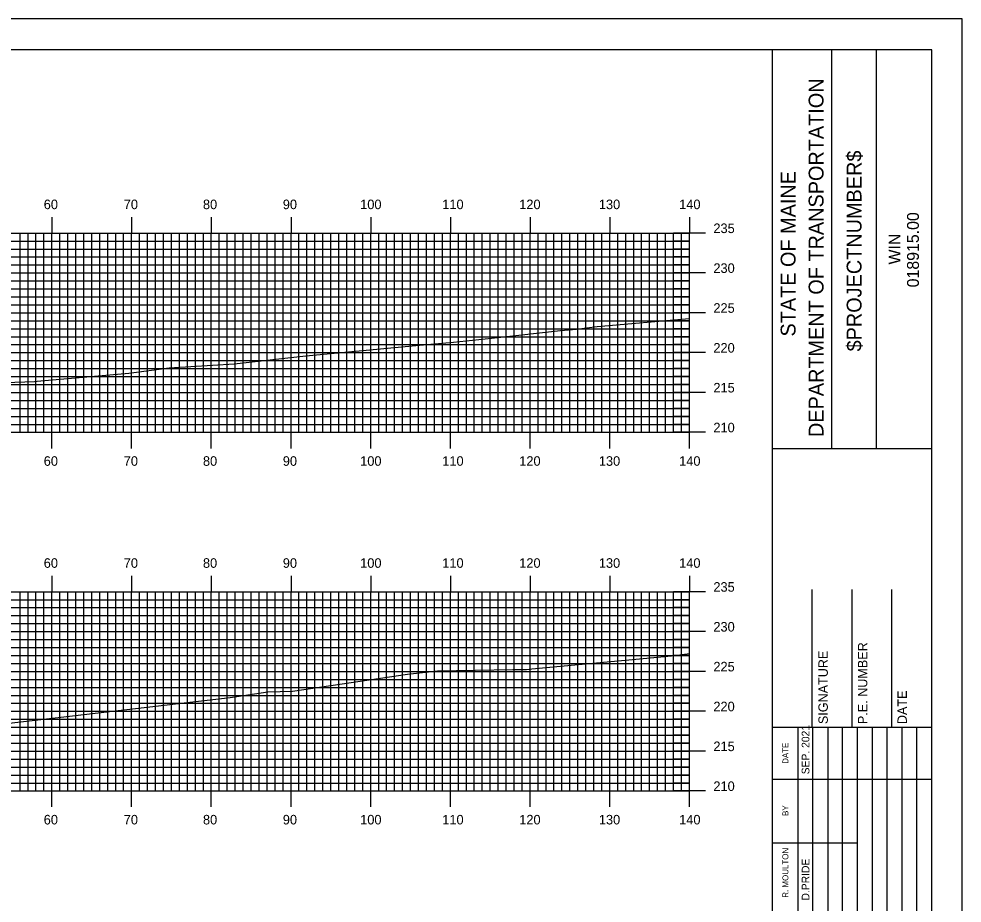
# Model space of a CAD drawing. Extents: x 1818850 to 1819194, y 442591 to 442811.
# Drawn here: x 1819072 to 1819190.4, y 442699.6 to 442810.5 of the extents above; entities that cross this region are included whole.
import ezdxf

# ---------------------------------------------------------------- set-up
doc = ezdxf.new("R2010")
doc.units = 0
for name, color, linetype in [('BORDER', 7, 'Continuous'), ('H_V ANNOTATION', 7, 'Continuous'), ('MAJOR', 7, 'Continuous'), ('MINOR', 7, 'Continuous'), ('PLOT BOUNDARY', 7, 'Continuous'), ('S_Roadway_Centerline', 7, 'Continuous')]:
    doc.layers.add(name, color=color, linetype=linetype)

msp = doc.modelspace()

# ---------------------------------------------------------------- linework, layer by layer
at = {"layer": 'BORDER'}
for p, q in [((1819166.55, 442596.67), (1819166.55, 442806.67)), ((1819174.01, 442756.66), (1819174.01, 442806.66)), ((1819179.6, 442756.66), (1819179.6, 442806.66)), ((1819166.55, 442756.65), (1819186.55, 442756.65)), ((1819171.55, 442721.67), (1819171.55, 442738.97)), ((1819176.55, 442721.67), (1819176.55, 442738.97)), ((1819181.55, 442721.67), (1819181.55, 442738.97)), ((1819166.55, 442721.67), (1819186.55, 442721.67))]:
    msp.add_line(p, q, dxfattribs=at)
msp.add_lwpolyline([(1818866.55, 442596.67), (1819186.55, 442596.67), (1819186.55, 442806.67), (1818866.55, 442806.67)], close=True, dxfattribs=at)
for points in [[(1819169.78, 442715.17), (1819169.78, 442721.67)], [(1819171.65, 442686.68), (1819171.65, 442721.67)], [(1819173.51, 442721.67), (1819173.51, 442686.68)], [(1819175.37, 442686.68), (1819175.37, 442721.67)], [(1819177.24, 442686.68), (1819177.24, 442721.67)], [(1819179.1, 442686.68), (1819179.1, 442721.67)], [(1819180.96, 442686.68), (1819180.96, 442721.67)], [(1819182.83, 442686.68), (1819182.83, 442721.67)], [(1819184.69, 442686.68), (1819184.69, 442721.67)], [(1819169.78, 442686.68), (1819169.78, 442720.26)], [(1819166.55, 442715.17), (1819186.55, 442715.17)], [(1819166.55, 442707.17), (1819169.78, 442707.17)], [(1819169.78, 442707.17), (1819177.23, 442707.17)]]:
    msp.add_lwpolyline(points, dxfattribs=at)
at = {"layer": 'MAJOR'}
for p, q in [((1819076.15, 442785.67), (1819076.15, 442783.67)), ((1819086.15, 442785.67), (1819086.15, 442783.67)), ((1819096.15, 442785.67), (1819096.15, 442783.67)), ((1819106.15, 442785.67), (1819106.15, 442783.67)), ((1819116.15, 442785.67), (1819116.15, 442783.67)), ((1819126.15, 442785.67), (1819126.15, 442783.67)), ((1819136.15, 442785.67), (1819136.15, 442783.67)), ((1819146.15, 442785.67), (1819146.15, 442783.67)), ((1819156.15, 442785.67), (1819156.15, 442783.67)), ((1818876.15, 442783.67), (1819156.15, 442783.67)), ((1818876.15, 442783.67), (1819156.15, 442783.67)), ((1819076.15, 442758.67), (1819076.15, 442783.67)), ((1819086.15, 442758.67), (1819086.15, 442783.67)), ((1819096.15, 442758.67), (1819096.15, 442783.67)), ((1819106.15, 442758.67), (1819106.15, 442783.67)), ((1819116.15, 442758.67), (1819116.15, 442783.67)), ((1819126.15, 442758.67), (1819126.15, 442783.67)), ((1819136.15, 442758.67), (1819136.15, 442783.67)), ((1819146.15, 442758.67), (1819146.15, 442783.67)), ((1819158.16, 442783.67), (1819154.15, 442783.67)), ((1819156.15, 442758.67), (1819156.15, 442783.67)), ((1819156.15, 442758.67), (1819156.15, 442783.67)), ((1818876.15, 442778.67), (1819156.15, 442778.67)), ((1819158.16, 442778.67), (1819154.15, 442778.67)), ((1818876.15, 442773.67), (1819156.15, 442773.67)), ((1819158.16, 442773.67), (1819154.15, 442773.67)), ((1818876.15, 442768.67), (1819156.15, 442768.67)), ((1819158.16, 442768.67), (1819154.15, 442768.67)), ((1818876.15, 442763.67), (1819156.15, 442763.67)), ((1819158.16, 442763.67), (1819154.15, 442763.67)), ((1818876.15, 442758.67), (1819156.15, 442758.67)), ((1818876.15, 442758.67), (1819156.15, 442758.67)), ((1819076.15, 442756.66), (1819076.15, 442758.67)), ((1819086.15, 442756.66), (1819086.15, 442758.67)), ((1819096.15, 442756.66), (1819096.15, 442758.67)), ((1819106.15, 442756.66), (1819106.15, 442758.67)), ((1819116.15, 442756.66), (1819116.15, 442758.67)), ((1819126.15, 442756.66), (1819126.15, 442758.67)), ((1819136.15, 442756.66), (1819136.15, 442758.67)), ((1819146.15, 442756.66), (1819146.15, 442758.67)), ((1819158.16, 442758.67), (1819154.15, 442758.67)), ((1819156.15, 442756.66), (1819156.15, 442758.67)), ((1819076.15, 442740.67), (1819076.15, 442738.67)), ((1819086.15, 442740.67), (1819086.15, 442738.67)), ((1819096.15, 442740.67), (1819096.15, 442738.67)), ((1819106.15, 442740.67), (1819106.15, 442738.67)), ((1819116.15, 442740.67), (1819116.15, 442738.67)), ((1819126.15, 442740.67), (1819126.15, 442738.67)), ((1819136.15, 442740.67), (1819136.15, 442738.67)), ((1819146.15, 442740.67), (1819146.15, 442738.67)), ((1819156.15, 442740.67), (1819156.15, 442738.67)), ((1818876.15, 442738.67), (1819156.15, 442738.67)), ((1818876.15, 442738.67), (1819156.15, 442738.67)), ((1819076.15, 442713.67), (1819076.15, 442738.67)), ((1819086.15, 442713.67), (1819086.15, 442738.67)), ((1819096.15, 442713.67), (1819096.15, 442738.67)), ((1819106.15, 442713.67), (1819106.15, 442738.67)), ((1819116.15, 442713.67), (1819116.15, 442738.67)), ((1819126.15, 442713.67), (1819126.15, 442738.67)), ((1819136.15, 442713.67), (1819136.15, 442738.67)), ((1819146.15, 442713.67), (1819146.15, 442738.67)), ((1819158.16, 442738.67), (1819154.15, 442738.67)), ((1819156.15, 442713.67), (1819156.15, 442738.67)), ((1819156.15, 442713.67), (1819156.15, 442738.67)), ((1818876.15, 442733.67), (1819156.15, 442733.67)), ((1819158.16, 442733.67), (1819154.15, 442733.67)), ((1818876.15, 442728.67), (1819156.15, 442728.67)), ((1819158.16, 442728.67), (1819154.15, 442728.67)), ((1818876.15, 442723.67), (1819156.15, 442723.67)), ((1819158.16, 442723.67), (1819154.15, 442723.67)), ((1818876.15, 442718.67), (1819156.15, 442718.67)), ((1819158.16, 442718.67), (1819154.15, 442718.67)), ((1818876.15, 442713.67), (1819156.15, 442713.67)), ((1818876.15, 442713.67), (1819156.15, 442713.67)), ((1819076.15, 442711.66), (1819076.15, 442713.67)), ((1819086.15, 442711.66), (1819086.15, 442713.67)), ((1819096.15, 442711.66), (1819096.15, 442713.67)), ((1819106.15, 442711.66), (1819106.15, 442713.67)), ((1819116.15, 442711.66), (1819116.15, 442713.67)), ((1819126.15, 442711.66), (1819126.15, 442713.67)), ((1819136.15, 442711.66), (1819136.15, 442713.67)), ((1819146.15, 442711.66), (1819146.15, 442713.67)), ((1819158.16, 442713.67), (1819154.15, 442713.67)), ((1819156.15, 442711.66), (1819156.15, 442713.67))]:
    msp.add_line(p, q, dxfattribs=at)
at = {"layer": 'MINOR'}
for p, q in [((1818876.15, 442782.67), (1819156.15, 442782.67)), ((1819072.15, 442758.67), (1819072.15, 442783.67)), ((1819073.15, 442758.67), (1819073.15, 442783.67)), ((1819074.15, 442758.67), (1819074.15, 442783.67)), ((1819075.15, 442758.67), (1819075.15, 442783.67)), ((1819077.15, 442758.67), (1819077.15, 442783.67)), ((1819078.15, 442758.67), (1819078.15, 442783.67)), ((1819079.15, 442758.67), (1819079.15, 442783.67)), ((1819080.15, 442758.67), (1819080.15, 442783.67)), ((1819081.15, 442758.67), (1819081.15, 442783.67)), ((1819082.15, 442758.67), (1819082.15, 442783.67)), ((1819083.15, 442758.67), (1819083.15, 442783.67)), ((1819084.15, 442758.67), (1819084.15, 442783.67)), ((1819085.15, 442758.67), (1819085.15, 442783.67)), ((1819087.15, 442758.67), (1819087.15, 442783.67)), ((1819088.15, 442758.67), (1819088.15, 442783.67)), ((1819089.15, 442758.67), (1819089.15, 442783.67)), ((1819090.15, 442758.67), (1819090.15, 442783.67)), ((1819091.15, 442758.67), (1819091.15, 442783.67)), ((1819092.15, 442758.67), (1819092.15, 442783.67)), ((1819093.15, 442758.67), (1819093.15, 442783.67)), ((1819094.15, 442758.67), (1819094.15, 442783.67)), ((1819095.15, 442758.67), (1819095.15, 442783.67)), ((1819097.15, 442758.67), (1819097.15, 442783.67)), ((1819098.15, 442758.67), (1819098.15, 442783.67)), ((1819099.15, 442758.67), (1819099.15, 442783.67)), ((1819100.15, 442758.67), (1819100.15, 442783.67)), ((1819101.15, 442758.67), (1819101.15, 442783.67)), ((1819102.15, 442758.67), (1819102.15, 442783.67)), ((1819103.15, 442758.67), (1819103.15, 442783.67)), ((1819104.15, 442758.67), (1819104.15, 442783.67)), ((1819105.15, 442758.67), (1819105.15, 442783.67)), ((1819107.15, 442758.67), (1819107.15, 442783.67)), ((1819108.15, 442758.67), (1819108.15, 442783.67)), ((1819109.15, 442758.67), (1819109.15, 442783.67)), ((1819110.15, 442758.67), (1819110.15, 442783.67)), ((1819111.15, 442758.67), (1819111.15, 442783.67)), ((1819112.15, 442758.67), (1819112.15, 442783.67)), ((1819113.15, 442758.67), (1819113.15, 442783.67)), ((1819114.15, 442758.67), (1819114.15, 442783.67)), ((1819115.15, 442758.67), (1819115.15, 442783.67)), ((1819117.15, 442758.67), (1819117.15, 442783.67)), ((1819118.15, 442758.67), (1819118.15, 442783.67)), ((1819119.15, 442758.67), (1819119.15, 442783.67)), ((1819120.15, 442758.67), (1819120.15, 442783.67)), ((1819121.15, 442758.67), (1819121.15, 442783.67)), ((1819122.15, 442758.67), (1819122.15, 442783.67)), ((1819123.15, 442758.67), (1819123.15, 442783.67)), ((1819124.15, 442758.67), (1819124.15, 442783.67)), ((1819125.15, 442758.67), (1819125.15, 442783.67)), ((1819127.15, 442758.67), (1819127.15, 442783.67)), ((1819128.15, 442758.67), (1819128.15, 442783.67)), ((1819129.15, 442758.67), (1819129.15, 442783.67)), ((1819130.15, 442758.67), (1819130.15, 442783.67)), ((1819131.15, 442758.67), (1819131.15, 442783.67)), ((1819132.15, 442758.67), (1819132.15, 442783.67)), ((1819133.15, 442758.67), (1819133.15, 442783.67)), ((1819134.15, 442758.67), (1819134.15, 442783.67)), ((1819135.15, 442758.67), (1819135.15, 442783.67)), ((1819137.15, 442758.67), (1819137.15, 442783.67)), ((1819138.15, 442758.67), (1819138.15, 442783.67)), ((1819139.15, 442758.67), (1819139.15, 442783.67)), ((1819140.15, 442758.67), (1819140.15, 442783.67)), ((1819141.15, 442758.67), (1819141.15, 442783.67)), ((1819142.15, 442758.67), (1819142.15, 442783.67)), ((1819143.15, 442758.67), (1819143.15, 442783.67)), ((1819144.15, 442758.67), (1819144.15, 442783.67)), ((1819145.15, 442758.67), (1819145.15, 442783.67)), ((1819147.15, 442758.67), (1819147.15, 442783.67)), ((1819148.15, 442758.67), (1819148.15, 442783.67)), ((1819149.15, 442758.67), (1819149.15, 442783.67)), ((1819150.15, 442758.67), (1819150.15, 442783.67)), ((1819151.15, 442758.67), (1819151.15, 442783.67)), ((1819152.15, 442758.67), (1819152.15, 442783.67)), ((1819153.15, 442758.67), (1819153.15, 442783.67)), ((1819154.15, 442758.67), (1819154.15, 442783.67)), ((1819156.15, 442782.67), (1819154.15, 442782.67)), ((1819155.15, 442758.67), (1819155.15, 442783.67)), ((1818876.15, 442781.67), (1819156.15, 442781.67)), ((1819156.15, 442781.67), (1819154.15, 442781.67)), ((1818876.15, 442780.67), (1819156.15, 442780.67)), ((1819156.15, 442780.67), (1819154.15, 442780.67)), ((1818876.15, 442779.67), (1819156.15, 442779.67)), ((1819156.15, 442779.67), (1819154.15, 442779.67)), ((1818876.15, 442777.67), (1819156.15, 442777.67)), ((1819156.15, 442777.67), (1819154.15, 442777.67)), ((1818876.15, 442776.67), (1819156.15, 442776.67)), ((1818876.15, 442775.67), (1819156.15, 442775.67)), ((1819156.15, 442776.67), (1819154.15, 442776.67)), ((1819156.15, 442775.67), (1819154.15, 442775.67)), ((1818876.15, 442774.67), (1819156.15, 442774.67)), ((1819156.15, 442774.67), (1819154.15, 442774.67)), ((1818876.15, 442772.67), (1819156.15, 442772.67)), ((1819156.15, 442772.67), (1819154.15, 442772.67)), ((1818876.15, 442771.67), (1819156.15, 442771.67)), ((1819156.15, 442771.67), (1819154.15, 442771.67)), ((1818876.15, 442770.67), (1819156.15, 442770.67)), ((1818876.15, 442769.67), (1819156.15, 442769.67)), ((1819156.15, 442770.67), (1819154.15, 442770.67)), ((1819156.15, 442769.67), (1819154.15, 442769.67)), ((1818876.15, 442767.67), (1819156.15, 442767.67)), ((1819156.15, 442767.67), (1819154.15, 442767.67)), ((1818876.15, 442766.67), (1819156.15, 442766.67)), ((1819156.15, 442766.67), (1819154.15, 442766.67)), ((1818876.15, 442765.67), (1819156.15, 442765.67)), ((1819156.15, 442765.67), (1819154.15, 442765.67)), ((1818876.15, 442764.67), (1819156.15, 442764.67)), ((1819156.15, 442764.67), (1819154.15, 442764.67)), ((1818876.15, 442762.67), (1819156.15, 442762.67)), ((1819156.15, 442762.67), (1819154.15, 442762.67)), ((1818876.15, 442761.67), (1819156.15, 442761.67)), ((1819156.15, 442761.67), (1819154.15, 442761.67)), ((1818876.15, 442760.67), (1819156.15, 442760.67)), ((1819156.15, 442760.67), (1819154.15, 442760.67)), ((1818876.15, 442759.67), (1819156.15, 442759.67)), ((1819156.15, 442759.67), (1819154.15, 442759.67)), ((1819072.15, 442713.67), (1819072.15, 442738.67)), ((1819073.15, 442713.67), (1819073.15, 442738.67)), ((1819074.15, 442713.67), (1819074.15, 442738.67)), ((1819075.15, 442713.67), (1819075.15, 442738.67)), ((1819077.15, 442713.67), (1819077.15, 442738.67)), ((1819078.15, 442713.67), (1819078.15, 442738.67)), ((1819079.15, 442713.67), (1819079.15, 442738.67)), ((1819080.15, 442713.67), (1819080.15, 442738.67)), ((1819081.15, 442713.67), (1819081.15, 442738.67)), ((1819082.15, 442713.67), (1819082.15, 442738.67)), ((1819083.15, 442713.67), (1819083.15, 442738.67)), ((1819084.15, 442713.67), (1819084.15, 442738.67)), ((1819085.15, 442713.67), (1819085.15, 442738.67)), ((1819087.15, 442713.67), (1819087.15, 442738.67)), ((1819088.15, 442713.67), (1819088.15, 442738.67)), ((1819089.15, 442713.67), (1819089.15, 442738.67)), ((1819090.15, 442713.67), (1819090.15, 442738.67)), ((1819091.15, 442713.67), (1819091.15, 442738.67)), ((1819092.15, 442713.67), (1819092.15, 442738.67)), ((1819093.15, 442713.67), (1819093.15, 442738.67)), ((1819094.15, 442713.67), (1819094.15, 442738.67)), ((1819095.15, 442713.67), (1819095.15, 442738.67)), ((1819097.15, 442713.67), (1819097.15, 442738.67)), ((1819098.15, 442713.67), (1819098.15, 442738.67)), ((1819099.15, 442713.67), (1819099.15, 442738.67)), ((1819100.15, 442713.67), (1819100.15, 442738.67)), ((1819101.15, 442713.67), (1819101.15, 442738.67)), ((1819102.15, 442713.67), (1819102.15, 442738.67)), ((1819103.15, 442713.67), (1819103.15, 442738.67)), ((1819104.15, 442713.67), (1819104.15, 442738.67)), ((1819105.15, 442713.67), (1819105.15, 442738.67)), ((1819107.15, 442713.67), (1819107.15, 442738.67)), ((1819108.15, 442713.67), (1819108.15, 442738.67)), ((1819109.15, 442713.67), (1819109.15, 442738.67)), ((1819110.15, 442713.67), (1819110.15, 442738.67)), ((1819111.15, 442713.67), (1819111.15, 442738.67)), ((1819112.15, 442713.67), (1819112.15, 442738.67)), ((1819113.15, 442713.67), (1819113.15, 442738.67)), ((1819114.15, 442713.67), (1819114.15, 442738.67)), ((1819115.15, 442713.67), (1819115.15, 442738.67)), ((1819117.15, 442713.67), (1819117.15, 442738.67)), ((1819118.15, 442713.67), (1819118.15, 442738.67)), ((1819119.15, 442713.67), (1819119.15, 442738.67)), ((1819120.15, 442713.67), (1819120.15, 442738.67)), ((1819121.15, 442713.67), (1819121.15, 442738.67)), ((1819122.15, 442713.67), (1819122.15, 442738.67)), ((1819123.15, 442713.67), (1819123.15, 442738.67)), ((1819124.15, 442713.67), (1819124.15, 442738.67)), ((1819125.15, 442713.67), (1819125.15, 442738.67)), ((1819127.15, 442713.67), (1819127.15, 442738.67)), ((1819128.15, 442713.67), (1819128.15, 442738.67)), ((1819129.15, 442713.67), (1819129.15, 442738.67)), ((1819130.15, 442713.67), (1819130.15, 442738.67)), ((1819131.15, 442713.67), (1819131.15, 442738.67)), ((1819132.15, 442713.67), (1819132.15, 442738.67)), ((1819133.15, 442713.67), (1819133.15, 442738.67)), ((1819134.15, 442713.67), (1819134.15, 442738.67)), ((1819135.15, 442713.67), (1819135.15, 442738.67)), ((1819137.15, 442713.67), (1819137.15, 442738.67)), ((1819138.15, 442713.67), (1819138.15, 442738.67)), ((1819139.15, 442713.67), (1819139.15, 442738.67)), ((1819140.15, 442713.67), (1819140.15, 442738.67)), ((1819141.15, 442713.67), (1819141.15, 442738.67)), ((1819142.15, 442713.67), (1819142.15, 442738.67)), ((1819143.15, 442713.67), (1819143.15, 442738.67)), ((1819144.15, 442713.67), (1819144.15, 442738.67)), ((1819145.15, 442713.67), (1819145.15, 442738.67)), ((1819147.15, 442713.67), (1819147.15, 442738.67)), ((1819148.15, 442713.67), (1819148.15, 442738.67)), ((1819149.15, 442713.67), (1819149.15, 442738.67)), ((1819150.15, 442713.67), (1819150.15, 442738.67)), ((1819151.15, 442713.67), (1819151.15, 442738.67)), ((1819152.15, 442713.67), (1819152.15, 442738.67)), ((1819153.15, 442713.67), (1819153.15, 442738.67)), ((1819154.15, 442713.67), (1819154.15, 442738.67)), ((1819155.15, 442713.67), (1819155.15, 442738.67)), ((1818876.15, 442737.67), (1819156.15, 442737.67)), ((1818876.15, 442736.67), (1819156.15, 442736.67)), ((1819156.15, 442737.67), (1819154.15, 442737.67)), ((1819156.15, 442736.67), (1819154.15, 442736.67)), ((1818876.15, 442735.67), (1819156.15, 442735.67)), ((1819156.15, 442735.67), (1819154.15, 442735.67)), ((1818876.15, 442734.67), (1819156.15, 442734.67)), ((1819156.15, 442734.67), (1819154.15, 442734.67)), ((1818876.15, 442732.67), (1819156.15, 442732.67)), ((1819156.15, 442732.67), (1819154.15, 442732.67)), ((1818876.15, 442731.67), (1819156.15, 442731.67)), ((1818876.15, 442730.67), (1819156.15, 442730.67)), ((1819156.15, 442731.67), (1819154.15, 442731.67)), ((1819156.15, 442730.67), (1819154.15, 442730.67)), ((1818876.15, 442729.67), (1819156.15, 442729.67)), ((1819156.15, 442729.67), (1819154.15, 442729.67)), ((1818876.15, 442727.67), (1819156.15, 442727.67)), ((1819156.15, 442727.67), (1819154.15, 442727.67)), ((1818876.15, 442726.67), (1819156.15, 442726.67)), ((1819156.15, 442726.67), (1819154.15, 442726.67)), ((1818876.15, 442725.67), (1819156.15, 442725.67)), ((1819156.15, 442725.67), (1819154.15, 442725.67)), ((1818876.15, 442724.67), (1819156.15, 442724.67)), ((1819156.15, 442724.67), (1819154.15, 442724.67)), ((1818876.15, 442722.67), (1819156.15, 442722.67)), ((1819156.15, 442722.67), (1819154.15, 442722.67)), ((1818876.15, 442721.67), (1819156.15, 442721.67)), ((1819156.15, 442721.67), (1819154.15, 442721.67)), ((1818876.15, 442720.67), (1819156.15, 442720.67)), ((1819156.15, 442720.67), (1819154.15, 442720.67)), ((1818876.15, 442719.67), (1819156.15, 442719.67)), ((1819156.15, 442719.67), (1819154.15, 442719.67)), ((1818876.15, 442717.67), (1819156.15, 442717.67)), ((1819156.15, 442717.67), (1819154.15, 442717.67)), ((1818876.15, 442716.67), (1819156.15, 442716.67)), ((1819156.15, 442716.67), (1819154.15, 442716.67)), ((1818876.15, 442715.67), (1819156.15, 442715.67)), ((1819156.15, 442715.67), (1819154.15, 442715.67)), ((1818876.15, 442714.67), (1819156.15, 442714.67)), ((1819156.15, 442714.67), (1819154.15, 442714.67))]:
    msp.add_line(p, q, dxfattribs=at)
at = {"layer": 'PLOT BOUNDARY'}
msp.add_lwpolyline([(1818850.36, 442590.55), (1819190.36, 442590.55), (1819190.36, 442810.55), (1818850.36, 442810.55)], close=True, dxfattribs=at)
at = {"layer": 'S_Roadway_Centerline'}
for points in [[(1819070.3, 442764.93), (1819073.96, 442765.06), (1819074.29, 442765.08), (1819085.8, 442766.09), (1819090.88, 442766.77), (1819099.03, 442767.28), (1819108.01, 442768.25), (1819121.83, 442769.57), (1819126.53, 442769.97), (1819132.12, 442770.57), (1819139.98, 442771.43), (1819141.96, 442771.62), (1819144.58, 442771.94), (1819156.15, 442772.95)], [(1819070.09, 442722.09), (1819098.53, 442725.38), (1819103.26, 442726.09), (1819106.34, 442726.19), (1819120.77, 442728.34), (1819124.55, 442728.74), (1819133.99, 442728.92), (1819135.71, 442728.93), (1819136.38, 442728.99), (1819152.14, 442730.47), (1819154.3, 442730.67), (1819156.15, 442730.92)]]:
    msp.add_lwpolyline(points, dxfattribs=at)

# ---------------------------------------------------------------- texts
at = {"layer": 'BORDER'}
for s, height, p in [('DEPARTMENT OF TRANSPORTATION', 1.8635, (1819172.97, 442758.08)), ('$PROJECTNUMBER$', 1.8635, (1819177.74, 442768.82)), ('STATE OF MAINE', 1.8635, (1819169.46, 442770.69)), ('018915.00', 1.491, (1819184.94, 442776.86)), ('WIN', 1.491, (1819182.63, 442779.73)), ('P.E. NUMBER', 1.1811, (1819178.47, 442722.06)), ('SIGNATURE', 1.181, (1819173.51, 442722.06)), ('DATE', 1.181, (1819183.43, 442722.06)), ('SEP. 2021', 0.969, (1819171.2, 442715.76)), ('DATE', 0.743, (1819168.56, 442717.08)), ('BY', 0.743, (1819168.56, 442710.54)), ('R. MOULTON', 0.745, (1819168.56, 442700.28)), ('D.PRIDE', 0.969, (1819171.2, 442699.92))]:
    msp.add_text(s, height=height, rotation=90, dxfattribs=at).set_placement(p)
at = {"layer": 'H_V ANNOTATION'}
for s, p in [('60', (1819075.12, 442786.67)), ('70', (1819085.16, 442786.67)), ('80', (1819095.1, 442786.67)), ('90', (1819105.12, 442786.67)), ('100', (1819114.83, 442786.67)), ('110', (1819125.13, 442786.67)), ('120', (1819134.79, 442786.67)), ('130', (1819144.78, 442786.67)), ('140', (1819154.86, 442786.67)), ('235', (1819159.15, 442783.67)), ('230', (1819159.15, 442778.67)), ('225', (1819159.15, 442773.67)), ('220', (1819159.15, 442768.67)), ('215', (1819159.15, 442763.67)), ('210', (1819159.15, 442758.67)), ('60', (1819075.12, 442754.47)), ('70', (1819085.16, 442754.47)), ('80', (1819095.1, 442754.47)), ('90', (1819105.12, 442754.47)), ('100', (1819114.83, 442754.47)), ('110', (1819125.13, 442754.47)), ('120', (1819134.79, 442754.47)), ('130', (1819144.78, 442754.47)), ('140', (1819154.86, 442754.47)), ('60', (1819075.12, 442741.67)), ('70', (1819085.16, 442741.67)), ('80', (1819095.1, 442741.67)), ('90', (1819105.12, 442741.67)), ('100', (1819114.83, 442741.67)), ('110', (1819125.13, 442741.67)), ('120', (1819134.79, 442741.67)), ('130', (1819144.78, 442741.67)), ('140', (1819154.86, 442741.67)), ('235', (1819159.15, 442738.67)), ('230', (1819159.15, 442733.67)), ('225', (1819159.15, 442728.67)), ('220', (1819159.15, 442723.67)), ('215', (1819159.15, 442718.67)), ('210', (1819159.15, 442713.67)), ('60', (1819075.12, 442709.47)), ('70', (1819085.16, 442709.47)), ('80', (1819095.1, 442709.47)), ('90', (1819105.12, 442709.47)), ('100', (1819114.83, 442709.47)), ('110', (1819125.13, 442709.47)), ('120', (1819134.79, 442709.47)), ('130', (1819144.78, 442709.47)), ('140', (1819154.86, 442709.47))]:
    msp.add_text(s, height=1.2, dxfattribs=at).set_placement(p)

doc.saveas('drawing.dxf')
